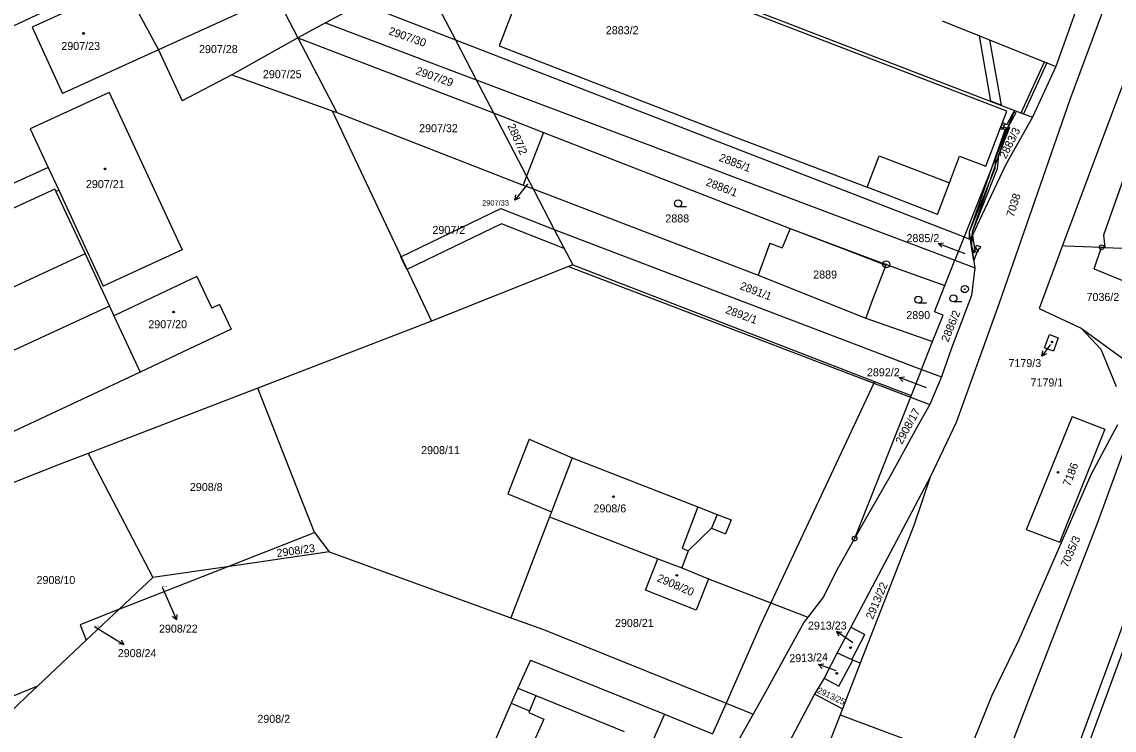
# Model space of a CAD drawing. Extents: x -593183 to -588034, y -1130415 to -1124994.
# Drawn here: x -591573.4 to -591341.4, y -1128134.3 to -1127983.9 of the extents above; entities that cross this region are included whole.
import ezdxf

# ---------------------------------------------------------------- set-up
doc = ezdxf.new("R2010")
doc.units = 0
for name, color, linetype in [('Vrstva 1', 7, 'Continuous'), ('Vrstva 16', 7, 'Continuous'), ('Vrstva 18', 7, 'Continuous'), ('Vrstva 19', 7, 'Continuous'), ('Vrstva 24', 7, 'Continuous'), ('Vrstva 25', 7, 'Continuous'), ('Vrstva 27', 7, 'Continuous'), ('Vrstva 4', 7, 'Continuous')]:
    doc.layers.add(name, color=color, linetype=linetype)

msp = doc.modelspace()

# ---------------------------------------------------------------- linework, layer by layer
at = {"layer": 'Vrstva 1'}
for p, q in [((-591318.29, -1127894.07), (-591353.86, -1127993.33)), ((-591317.66, -1127911.4), (-591350.8, -1128000.19)), ((-591527.67, -1127962.28), (-591514.76, -1127987.24)), ((-591467.59, -1127962.25), (-591362.61, -1128002.67)), ((-591462.75, -1127964.81), (-591472.01, -1127988.94)), ((-591327.4, -1127964.65), (-591344.16, -1128009.18)), ((-591553.24, -1127974.41), (-591673.98, -1128031.42)), ((-591551.76, -1127976.15), (-591571.16, -1127985)), ((-591551.76, -1127976.15), (-591544.34, -1127989.79)), ((-591289.77, -1127976.8), (-591349.4, -1128138.35)), ((-591520.52, -1127978.94), (-591544.34, -1127989.79)), ((-591501.18, -1127979.96), (-591508.9, -1127984.1)), ((-591501.18, -1127979.96), (-591481.32, -1127987.66)), ((-591485.52, -1127979.6), (-591481.32, -1127987.66)), ((-591571.16, -1127985), (-591564.7, -1127999.07)), ((-591508.9, -1127984.1), (-591514.76, -1127987.24)), ((-591508.9, -1127984.1), (-591476.88, -1127996.17)), ((-591377.94, -1127983.65), (-591353.86, -1127993.33)), ((-591514.76, -1127987.24), (-591528.79, -1127995.15)), ((-591514.76, -1127987.24), (-591473.22, -1128003.19)), ((-591514.76, -1127987.24), (-591506.5, -1128003.12)), ((-591481.32, -1127987.66), (-591476.88, -1127996.17)), ((-591481.32, -1127987.66), (-591373.3, -1128029.54)), ((-591544.34, -1127989.79), (-591564.7, -1127999.07)), ((-591544.34, -1127989.79), (-591539.32, -1128000.67)), ((-591353.86, -1127993.33), (-591358.81, -1128004.13)), ((-591528.79, -1127995.15), (-591539.32, -1128000.67)), ((-591528.79, -1127995.15), (-591507.49, -1128002.77)), ((-591476.88, -1127996.17), (-591473.22, -1128003.19)), ((-591476.88, -1127996.17), (-591375.26, -1128034.5)), ((-591554.81, -1127998.91), (-591571.56, -1128006.6)), ((-591554.81, -1127998.91), (-591539.33, -1128032.27)), ((-591350.8, -1128000.19), (-591365.86, -1128043.58)), ((-591333.81, -1128001.04), (-591343.68, -1128029.17)), ((-591507.49, -1128002.77), (-591506.5, -1128003.12)), ((-591507.49, -1128002.77), (-591486.4, -1128047.45)), ((-591506.5, -1128003.12), (-591466.91, -1128018.52)), ((-591473.22, -1128003.19), (-591462.58, -1128007.34)), ((-591473.22, -1128003.19), (-591466.19, -1128016.67)), ((-591362.61, -1128002.67), (-591373.3, -1128029.54)), ((-591368.7, -1128014.53), (-591364.24, -1128002.85)), ((-591362.61, -1128002.67), (-591358.81, -1128004.13)), ((-591358.81, -1128004.13), (-591364.45, -1128014.17)), ((-591571.56, -1128006.6), (-591567.77, -1128014.77)), ((-591462.58, -1128007.34), (-591466.19, -1128016.67)), ((-591462.58, -1128007.34), (-591410.23, -1128027.74)), ((-591344.16, -1128009.18), (-591352.42, -1128031.38)), ((-591376.42, -1128018.07), (-591374.27, -1128012.37)), ((-591374.27, -1128012.37), (-591368.7, -1128014.53)), ((-591567.77, -1128014.77), (-591577.51, -1128019.24)), ((-591567.77, -1128014.77), (-591565.52, -1128019.65)), ((-591364.45, -1128014.17), (-591369.53, -1128024.89)), ((-591466.19, -1128016.67), (-591466.91, -1128018.52)), ((-591466.19, -1128016.67), (-591464.81, -1128019.33)), ((-591566.36, -1128019.38), (-591623.78, -1128045.8)), ((-591566.36, -1128019.38), (-591566.11, -1128019.92)), ((-591565.52, -1128019.65), (-591566.11, -1128019.92)), ((-591566.11, -1128019.92), (-591559.94, -1128033.16)), ((-591565.52, -1128019.65), (-591556.09, -1128040.03)), ((-591466.91, -1128018.52), (-591464.81, -1128019.33)), ((-591464.81, -1128019.33), (-591417.01, -1128037.68)), ((-591464.81, -1128019.33), (-591460.31, -1128027.95)), ((-591378.98, -1128024.81), (-591393.89, -1128019)), ((-591378.98, -1128024.81), (-591376.42, -1128018.07)), ((-591369.53, -1128024.89), (-591371.94, -1128030.07)), ((-591460.31, -1128027.95), (-591456.4, -1128035.45)), ((-591460.31, -1128027.95), (-591382.32, -1128057.66)), ((-591410.23, -1128027.74), (-591411.94, -1128031.87)), ((-591410.23, -1128027.74), (-591389.83, -1128035.38)), ((-591343.68, -1128029.17), (-591343.41, -1128031.78)), ((-591414.55, -1128030.87), (-591417.01, -1128037.68)), ((-591414.55, -1128030.87), (-591411.94, -1128031.87)), ((-591373.3, -1128029.54), (-591375.26, -1128034.5)), ((-591373.3, -1128029.54), (-591371.94, -1128030.07)), ((-591371.94, -1128030.07), (-591371.04, -1128036.09)), ((-591352.42, -1128031.38), (-591357.39, -1128044.74)), ((-591352.42, -1128031.38), (-591351.76, -1128031.41)), ((-591351.76, -1128031.41), (-591344.12, -1128031.75)), ((-591345.72, -1128036.35), (-591344.12, -1128031.75)), ((-591344.12, -1128031.75), (-591343.41, -1128031.78)), ((-591559.94, -1128033.16), (-591599.4, -1128051.4)), ((-591559.94, -1128033.16), (-591554.77, -1128044.23)), ((-591539.33, -1128032.27), (-591556.09, -1128040.03)), ((-591343.41, -1128031.78), (-591326.94, -1128032.5)), ((-591457.32, -1128035.82), (-591486.4, -1128047.45)), ((-591456.4, -1128035.45), (-591457.32, -1128035.82)), ((-591457.32, -1128035.82), (-591392.49, -1128060.57)), ((-591389.95, -1128035.52), (-591393.01, -1128043.64)), ((-591389.83, -1128035.38), (-591389.95, -1128035.52)), ((-591389.83, -1128035.38), (-591377.41, -1128039.89)), ((-591377.41, -1128039.89), (-591375.26, -1128034.5)), ((-591375.26, -1128034.5), (-591371.04, -1128036.09)), ((-591371.04, -1128036.09), (-591371.74, -1128041.95)), ((-591345.72, -1128036.35), (-591329.58, -1128042.89)), ((-591536.19, -1128037.97), (-591553.8, -1128046.31)), ((-591536.19, -1128037.97), (-591533.03, -1128044.65)), ((-591417.01, -1128037.68), (-591394.2, -1128046.78)), ((-591371.74, -1128041.95), (-591375.97, -1128053.19)), ((-591554.77, -1128044.23), (-591594.16, -1128062.43)), ((-591554.77, -1128044.23), (-591553.8, -1128046.31)), ((-591531.36, -1128043.86), (-591533.03, -1128044.65)), ((-591531.36, -1128043.86), (-591528.89, -1128049.13)), ((-591393.01, -1128043.64), (-591394.2, -1128046.78)), ((-591365.86, -1128043.58), (-591374.99, -1128068.94)), ((-591357.39, -1128044.74), (-591348.46, -1128048.94)), ((-591553.8, -1128046.31), (-591548.21, -1128058.27)), ((-591486.4, -1128047.45), (-591523.28, -1128061.64)), ((-591394.2, -1128046.78), (-591379.99, -1128051.78)), ((-591528.89, -1128049.13), (-591548.21, -1128058.27)), ((-591356.22, -1128053.08), (-591355.17, -1128050.27)), ((-591355.17, -1128050.27), (-591353.3, -1128050.97)), ((-591348.46, -1128048.94), (-591344.28, -1128053.4)), ((-591348.46, -1128048.94), (-591337.8, -1128056.63)), ((-591382.32, -1128057.66), (-591379.99, -1128051.78)), ((-591353.3, -1128050.97), (-591354.34, -1128053.77)), ((-591375.97, -1128053.19), (-591378.13, -1128059.26)), ((-591354.34, -1128053.77), (-591356.22, -1128053.08)), ((-591344.28, -1128053.4), (-591341.04, -1128061.29)), ((-591548.21, -1128058.27), (-591602.93, -1128083.84)), ((-591382.32, -1128057.66), (-591384.52, -1128063.22)), ((-591382.32, -1128057.66), (-591378.13, -1128059.26)), ((-591378.13, -1128059.26), (-591380.46, -1128064.79)), ((-591523.28, -1128061.64), (-591559.28, -1128075.5)), ((-591511.23, -1128092.29), (-591523.28, -1128061.64)), ((-591392.49, -1128060.57), (-591384.66, -1128063.56)), ((-591384.66, -1128063.56), (-591396.57, -1128093.61)), ((-591384.52, -1128063.22), (-591384.66, -1128063.56)), ((-591384.66, -1128063.56), (-591380.59, -1128065.11)), ((-591335.23, -1128063.42), (-591345.05, -1128090.42)), ((-591380.59, -1128065.11), (-591383.26, -1128069.89)), ((-591380.46, -1128064.79), (-591380.59, -1128065.11)), ((-591350.39, -1128067.64), (-591359.66, -1128090.51)), ((-591350.39, -1128067.64), (-591343.45, -1128070.34)), ((-591383.26, -1128069.89), (-591389.02, -1128080.33)), ((-591374.99, -1128068.94), (-591380.52, -1128080.58)), ((-591343.45, -1128070.34), (-591352.47, -1128092.99)), ((-591340.75, -1128069.47), (-591346.41, -1128080.07)), ((-591465.63, -1128072.51), (-591470.14, -1128084.1)), ((-591465.63, -1128072.51), (-591456.51, -1128076.44)), ((-591559.28, -1128075.5), (-591565.82, -1128078)), ((-591559.28, -1128075.5), (-591545.54, -1128101.87)), ((-591565.82, -1128078), (-591649.36, -1128110.92)), ((-591456.51, -1128076.44), (-591429.84, -1128086.85)), ((-591389.02, -1128080.33), (-591393.05, -1128087.37)), ((-591346.41, -1128080.07), (-591361.7, -1128115.12)), ((-591380.52, -1128080.58), (-591397.34, -1128112.43)), ((-591380.52, -1128080.58), (-591383.99, -1128090.81)), ((-591470.14, -1128084.1), (-591460.88, -1128087.92)), ((-591327.13, -1128083.52), (-591347.63, -1128139.13)), ((-591429.84, -1128086.85), (-591425.75, -1128088.45)), ((-591393.05, -1128087.37), (-591396.57, -1128093.61)), ((-591461.3, -1128088.95), (-591469.51, -1128110.39)), ((-591460.88, -1128087.92), (-591461.3, -1128088.95)), ((-591461.3, -1128088.95), (-591438.31, -1128097.88)), ((-591425.75, -1128088.45), (-591422.77, -1128089.62)), ((-591422.77, -1128089.62), (-591423.93, -1128092.59)), ((-591426.91, -1128091.42), (-591431.86, -1128096.17)), ((-591426.91, -1128091.42), (-591423.93, -1128092.59)), ((-591383.99, -1128090.81), (-591395.38, -1128120.07)), ((-591359.66, -1128090.51), (-591360.14, -1128091.69)), ((-591360.14, -1128091.69), (-591353, -1128094.33)), ((-591345.05, -1128090.42), (-591359.82, -1128128.47)), ((-591529.74, -1128099.58), (-591511.23, -1128092.29)), ((-591511.23, -1128092.29), (-591508.14, -1128096.44)), ((-591396.57, -1128093.61), (-591400.63, -1128100.79)), ((-591352.47, -1128092.99), (-591353, -1128094.33)), ((-591509.53, -1128096.64), (-591529.74, -1128099.58)), ((-591508.14, -1128096.44), (-591509.53, -1128096.64)), ((-591508.14, -1128096.44), (-591469.51, -1128110.39)), ((-591431.86, -1128096.17), (-591433.26, -1128099.84)), ((-591438.31, -1128097.88), (-591433.26, -1128099.84)), ((-591552.71, -1128108.62), (-591529.74, -1128099.58)), ((-591529.74, -1128099.58), (-591545.54, -1128101.87)), ((-591433.26, -1128099.84), (-591427.6, -1128102.17)), ((-591400.63, -1128100.79), (-591403.14, -1128105.98)), ((-591545.54, -1128101.87), (-591552.71, -1128108.62)), ((-591427.6, -1128102.17), (-591414.32, -1128107.21)), ((-591414.32, -1128107.21), (-591406.45, -1128110.28)), ((-591403.14, -1128105.98), (-591406.45, -1128110.28)), ((-591552.71, -1128108.62), (-591560.99, -1128111.89)), ((-591552.71, -1128108.62), (-591559.68, -1128115.19)), ((-591469.51, -1128110.39), (-591462.57, -1128112.89)), ((-591406.45, -1128110.28), (-591407.23, -1128111.29)), ((-591560.99, -1128111.89), (-591559.68, -1128115.19)), ((-591462.57, -1128112.89), (-591423.83, -1128128.57)), ((-591407.23, -1128111.29), (-591415.39, -1128126.09)), ((-591397.34, -1128112.43), (-591400.22, -1128117.89)), ((-591397.34, -1128112.43), (-591394.4, -1128113.97)), ((-591559.68, -1128115.19), (-591570.02, -1128124.92)), ((-591397.17, -1128119.29), (-591394.4, -1128113.97)), ((-591361.7, -1128115.12), (-591367.39, -1128126.92)), ((-591465.35, -1128119.41), (-591468.07, -1128125.36)), ((-591465.35, -1128119.41), (-591436.9, -1128130.85)), ((-591400.22, -1128117.89), (-591403.02, -1128123.21)), ((-591400.22, -1128117.89), (-591397.17, -1128119.29)), ((-591399.87, -1128124.93), (-591396.9, -1128119.41)), ((-591396.9, -1128119.41), (-591397.17, -1128119.29)), ((-591395.38, -1128120.07), (-591396.9, -1128119.41)), ((-591395.38, -1128120.07), (-591399.14, -1128129.73)), ((-591403.02, -1128123.21), (-591405.04, -1128126.64)), ((-591403.02, -1128123.21), (-591399.87, -1128124.93)), ((-591570.02, -1128124.92), (-591630.51, -1128149.5)), ((-591570.02, -1128124.92), (-591572.28, -1128127.04)), ((-591468.07, -1128125.36), (-591469.47, -1128128.57)), ((-591415.39, -1128126.09), (-591418.1, -1128130.89)), ((-591405.04, -1128126.64), (-591412.55, -1128140.74)), ((-591405.04, -1128126.64), (-591404.88, -1128126.73)), ((-591404.88, -1128126.73), (-591399.14, -1128129.73)), ((-591572.28, -1128127.04), (-591581.11, -1128135.51)), ((-591469.47, -1128128.57), (-591478.53, -1128149.36)), ((-591423.83, -1128128.57), (-591418.1, -1128130.89)), ((-591359.82, -1128128.47), (-591382.83, -1128188.08)), ((-591367.39, -1128126.92), (-591373.09, -1128140.88)), ((-591436.9, -1128130.85), (-591426.69, -1128135.07)), ((-591418.37, -1128131.37), (-591421.57, -1128137.02)), ((-591418.1, -1128130.89), (-591418.37, -1128131.37)), ((-591399.65, -1128131.04), (-591411.36, -1128161.14)), ((-591399.14, -1128129.73), (-591399.65, -1128131.04)), ((-591399.65, -1128131.04), (-591373.09, -1128140.88))]:
    msp.add_line(p, q, dxfattribs=at)
for points in [[(-591364.24, -1128002.85), (-591411.69, -1127984.59), (-591462.75, -1127964.81)], [(-591472.01, -1127988.94), (-591420.94, -1128008.75), (-591393.89, -1128019)], [(-591379.99, -1128051.78), (-591377.77, -1128046.19), (-591379.62, -1128045.45), (-591377.41, -1128039.89)], [(-591427.6, -1128102.17), (-591430.22, -1128108.8), (-591440.91, -1128104.58), (-591438.31, -1128097.88)]]:
    msp.add_lwpolyline(points, dxfattribs=at)
at = {"layer": 'Vrstva 16'}
for p, q in [((-591466.02, -1128018.35), (-591466.82, -1128019.37)), ((-591373.09, -1128033.17), (-591376.02, -1128032.02)), ((-591381.29, -1128061.57), (-591384.29, -1128060.45)), ((-591543.53, -1128103.88), (-591541.72, -1128108.11)), ((-591557.96, -1128112.28), (-591554.24, -1128114.52)), ((-591396.9, -1128115.72), (-591397.9, -1128115.04)), ((-591400.48, -1128121.67), (-591401.39, -1128121.35))]:
    msp.add_line(p, q, dxfattribs=at)
at = {"layer": 'Vrstva 24'}
for centre, radius in [((-591344.12, -1128031.75), 0.5), ((-591344.12, -1128031.75), 0.0327), ((-591389.83, -1128035.38), 0.75), ((-591389.83, -1128035.38), 0.0903), ((-591373.15, -1128040.63), 0.75), ((-591373.15, -1128040.63), 0.0903), ((-591396.57, -1128093.61), 0.5), ((-591396.57, -1128093.61), 0.0327)]:
    msp.add_circle(centre, radius, dxfattribs=at)
at = {"layer": 'Vrstva 25'}
for p, q in [((-591466.82, -1128019.37), (-591468.66, -1128021.74)), ((-591432.27, -1128023.18), (-591434.02, -1128023.18)), ((-591376.02, -1128032.02), (-591378.81, -1128030.92)), ((-591381.28, -1128043.62), (-591383.03, -1128043.62)), ((-591373.81, -1128043.35), (-591375.56, -1128043.35)), ((-591355.02, -1128052.43), (-591356.77, -1128054.87)), ((-591384.29, -1128060.45), (-591387.1, -1128059.4)), ((-591541.72, -1128108.11), (-591540.54, -1128110.87)), ((-591554.24, -1128114.52), (-591551.67, -1128116.06)), ((-591397.9, -1128115.04), (-591400.38, -1128113.35)), ((-591401.39, -1128121.35), (-591404.22, -1128120.35))]:
    msp.add_line(p, q, dxfattribs=at)
for points in [[(-591467.65, -1128021.26), (-591468.66, -1128021.74), (-591468.44, -1128020.64)], [(-591378.06, -1128031.75), (-591378.81, -1128030.92), (-591377.7, -1128030.82)], [(-591355.78, -1128054.35), (-591356.77, -1128054.87), (-591356.59, -1128053.76)], [(-591386.34, -1128060.22), (-591387.1, -1128059.4), (-591385.99, -1128059.28)], [(-591540.47, -1128109.75), (-591540.54, -1128110.87), (-591541.39, -1128110.15)], [(-591552.27, -1128115.12), (-591551.67, -1128116.06), (-591552.78, -1128115.98)], [(-591399.83, -1128114.32), (-591400.38, -1128113.35), (-591399.27, -1128113.5)], [(-591403.44, -1128121.16), (-591404.22, -1128120.35), (-591403.11, -1128120.21)]]:
    msp.add_lwpolyline(points, dxfattribs=at)
for centre, radius in [((-591560.25, -1127986.34), 0.175), ((-591560.25, -1127986.34), 0.15), ((-591555.69, -1128015.09), 0.175), ((-591555.69, -1128015.09), 0.15), ((-591434.02, -1128022.43), 0.75), ((-591383.03, -1128042.87), 0.75), ((-591375.56, -1128042.6), 0.75), ((-591541.14, -1128045.49), 0.175), ((-591541.14, -1128045.49), 0.15), ((-591354.64, -1128051.84), 0.175), ((-591354.64, -1128051.84), 0.15), ((-591353.35, -1128079.52), 0.175), ((-591353.35, -1128079.52), 0.15), ((-591447.75, -1128084.71), 0.175), ((-591447.75, -1128084.71), 0.15), ((-591434.31, -1128101.41), 0.175), ((-591434.31, -1128101.41), 0.15), ((-591397.41, -1128116.76), 0.175), ((-591397.41, -1128116.76), 0.15), ((-591400.33, -1128122.2), 0.175), ((-591400.33, -1128122.2), 0.15)]:
    msp.add_circle(centre, radius, dxfattribs=at)
at = {"layer": 'Vrstva 27'}
for p, q in [((-591367.62, -1128000.74), (-591370.05, -1127986.82)), ((-591370.05, -1127986.82), (-591367.88, -1127987.69)), ((-591367.88, -1127987.69), (-591365.46, -1128001.57)), ((-591361.18, -1128003.22), (-591356.23, -1127992.38)), ((-591355.77, -1127992.56), (-591360.71, -1128003.4)), ((-591356.23, -1127992.38), (-591355.77, -1127992.56)), ((-591365.46, -1128001.57), (-591367.62, -1128000.74)), ((-591364.17, -1128005.59), (-591362.76, -1128002.99)), ((-591362.31, -1128003.2), (-591363.95, -1128006.14)), ((-591362.76, -1128002.99), (-591362.74, -1128003)), ((-591362.74, -1128003), (-591362.31, -1128003.2)), ((-591360.71, -1128003.4), (-591361.18, -1128003.22)), ((-591365.64, -1128006.53), (-591365.32, -1128005.69)), ((-591365.47, -1128006.25), (-591365.12, -1128005.28)), ((-591365.32, -1128005.69), (-591364.83, -1128005.91)), ((-591365.12, -1128005.28), (-591364.66, -1128005.44)), ((-591364.91, -1128006.17), (-591365, -1128006.42)), ((-591364.83, -1128005.91), (-591364.91, -1128006.17)), ((-591364.3, -1128006.52), (-591364.91, -1128006.17)), ((-591364.91, -1128006.17), (-591364.12, -1128006.47)), ((-591364.66, -1128005.44), (-591364.73, -1128005.67)), ((-591364.73, -1128005.67), (-591364.17, -1128005.59)), ((-591363.95, -1128006.14), (-591363.68, -1128006.3)), ((-591366.89, -1128013.43), (-591364.12, -1128006.47)), ((-591364.12, -1128006.47), (-591366.89, -1128013.43)), ((-591366.89, -1128013.43), (-591364.6, -1128006.79)), ((-591366.47, -1128012.21), (-591364.3, -1128006.52)), ((-591363.68, -1128006.3), (-591365.97, -1128012.29)), ((-591363.98, -1128006.53), (-591365.97, -1128012.29)), ((-591365.19, -1128006.73), (-591365.64, -1128006.53)), ((-591365, -1128006.42), (-591365.47, -1128006.25)), ((-591365.11, -1128006.55), (-591365.19, -1128006.73)), ((-591364.6, -1128006.79), (-591365.11, -1128006.55)), ((-591364.12, -1128006.47), (-591363.98, -1128006.53)), ((-591365.97, -1128012.29), (-591371.61, -1128028.5)), ((-591366.74, -1128014.95), (-591366.49, -1128012.43)), ((-591366.49, -1128012.43), (-591366.47, -1128012.21)), ((-591365.97, -1128012.29), (-591366.26, -1128015.09)), ((-591372.13, -1128028.44), (-591366.89, -1128013.43)), ((-591372.13, -1128028.44), (-591366.74, -1128014.95)), ((-591366.26, -1128015.09), (-591371.61, -1128028.5)), ((-591492.87, -1128033.75), (-591471.67, -1128023.48)), ((-591471.67, -1128023.48), (-591460.31, -1128027.95)), ((-591471.55, -1128026.76), (-591491.59, -1128036.46)), ((-591458.19, -1128032.01), (-591471.55, -1128026.76)), ((-591460.31, -1128027.95), (-591458.19, -1128032.01)), ((-591372.19, -1128029.97), (-591372.13, -1128028.44)), ((-591371.94, -1128030.07), (-591372.13, -1128028.44)), ((-591371.94, -1128030.07), (-591371.52, -1128029.17)), ((-591371.52, -1128029.17), (-591371.94, -1128030.07)), ((-591371.94, -1128030.07), (-591371.64, -1128029.43)), ((-591371.64, -1128029.43), (-591371.94, -1128030.07)), ((-591371.64, -1128029.43), (-591371.72, -1128031.56)), ((-591371.61, -1128028.5), (-591371.64, -1128029.43)), ((-591371.61, -1128028.5), (-591371.52, -1128029.17)), ((-591371.52, -1128029.17), (-591371.1, -1128032.1)), ((-591371.94, -1128030.07), (-591372.19, -1128029.97)), ((-591371.58, -1128032.47), (-591371.94, -1128030.07)), ((-591371.72, -1128031.56), (-591371.94, -1128030.07)), ((-591371.72, -1128031.56), (-591371.17, -1128032.92)), ((-591371.58, -1128032.47), (-591371.72, -1128031.56)), ((-591370.84, -1128031.77), (-591370.68, -1128031.31)), ((-591370.68, -1128031.31), (-591369.83, -1128031.6)), ((-591369.83, -1128031.6), (-591369.99, -1128032.06)), ((-591491.59, -1128036.46), (-591492.87, -1128033.75)), ((-591370.48, -1128032.85), (-591371.58, -1128032.47)), ((-591371.27, -1128034.55), (-591371.58, -1128032.47)), ((-591370.39, -1128032.22), (-591371.27, -1128034.55)), ((-591371.17, -1128032.92), (-591370.86, -1128032.05)), ((-591371.1, -1128032.1), (-591370.78, -1128032.21)), ((-591370.86, -1128032.05), (-591370.39, -1128032.22)), ((-591370.65, -1128031.86), (-591370.84, -1128031.77)), ((-591370.78, -1128032.21), (-591370.65, -1128031.86)), ((-591370.18, -1128032.03), (-591370.48, -1128032.85)), ((-591369.99, -1128032.06), (-591370.18, -1128032.03))]:
    msp.add_line(p, q, dxfattribs=at)
at = {"layer": 'Vrstva 4'}
for p, q in [((-591393.89, -1128019), (-591391.34, -1128012.33)), ((-591391.34, -1128012.33), (-591376.42, -1128018.07)), ((-591410.23, -1128027.74), (-591398.72, -1128032.15)), ((-591398.72, -1128032.15), (-591389.95, -1128035.52)), ((-591456.4, -1128035.45), (-591392.32, -1128060.21)), ((-591392.49, -1128060.57), (-591414.32, -1128107.21)), ((-591392.32, -1128060.21), (-591392.49, -1128060.57)), ((-591392.32, -1128060.21), (-591384.52, -1128063.22)), ((-591456.51, -1128076.44), (-591460.88, -1128087.92)), ((-591429.84, -1128086.85), (-591433.18, -1128095.66)), ((-591425.75, -1128088.45), (-591426.91, -1128091.42)), ((-591433.18, -1128095.66), (-591431.86, -1128096.17)), ((-591414.32, -1128107.21), (-591416.47, -1128111.8)), ((-591416.47, -1128111.8), (-591423.83, -1128128.57)), ((-591468.07, -1128125.36), (-591464.22, -1128126.93)), ((-591469.47, -1128128.57), (-591465.54, -1128130.17)), ((-591464.22, -1128126.93), (-591465.54, -1128130.17)), ((-591464.22, -1128126.93), (-591445.47, -1128134.57)), ((-591423.83, -1128128.57), (-591426.69, -1128135.07)), ((-591465.54, -1128130.17), (-591465.69, -1128130.54)), ((-591465.69, -1128130.54), (-591462.54, -1128131.96)), ((-591436.9, -1128130.85), (-591439.59, -1128136.97)), ((-591462.54, -1128131.96), (-591465.45, -1128138.44))]:
    msp.add_line(p, q, dxfattribs=at)

# ---------------------------------------------------------------- texts
at = {"layer": 'Vrstva 16'}
for s, height, p in [('2907/33', 1.14, (-591475.63, -1128022.88)), ('2885/2', 1.7, (-591385.53, -1128030.65)), ('7179/3', 1.7, (-591363.88, -1128057.18)), ('2892/2', 1.7, (-591393.93, -1128059.13)), ('7179/1', 1.7, (-591359.2, -1128061.29)), ('2908/22', 1.7, (-591544.24, -1128113.58)), ('2913/23', 1.7, (-591406.46, -1128112.92)), ('2908/24', 1.7, (-591552.99, -1128118.77))]:
    msp.add_text(s, height=height, dxfattribs=at).set_placement(p)
msp.add_text('2913/24', height=1.7, rotation=2.2453, dxfattribs=at).set_placement((-591410.38, -1128119.89))
at = {"layer": 'Vrstva 18'}
for s, height, rotation, p in [('2907/30', 1.7, 340.594, (-591495.63, -1127986.49)), ('2907/29', 1.7, 340.594, (-591489.88, -1127994.95)), ('2887/2', 1.7, 293.8388, (-591470.31, -1128005.94)), ('2883/3', 1.7, 63.435, (-591364.43, -1128013.07)), ('2885/1', 1.7, 339.3348, (-591425.48, -1128013.34)), ('2886/1', 1.7, 338.7099, (-591428.28, -1128018.54)), ('7038', 1.7, 72.4076, (-591362.78, -1128025.44)), ('2891/1', 1.7, 339.1435, (-591421.05, -1128040.59)), ('2892/1', 1.7, 339.7936, (-591424.1, -1128045.67)), ('2886/2', 1.7, 67.8214, (-591376.67, -1128052)), ('2908/17', 1.7, 61.1226, (-591386.52, -1128073.74)), ('7035/3', 1.7, 66.6445, (-591351.33, -1128099.87)), ('2908/23', 1.7, 7.8792, (-591519.15, -1128097.54)), ('2913/22', 1.7, 66.8792, (-591392.69, -1128110.88)), ('2913/25', 1.3, 334.8407, (-591404.6, -1128126.29))]:
    msp.add_text(s, height=height, rotation=rotation, dxfattribs=at).set_placement(p)
for s, height, p in [('2907/28', 1.7, (-591535.74, -1127990.51)), ('2907/25', 1.7, (-591522.18, -1127995.84)), ('2907/32', 1.7, (-591489.01, -1128007.31)), ('2907/33', 0.1, (-591466.02, -1128018.35)), ('2888', 1.7, (-591436.73, -1128026.47)), ('2907/2', 1.7, (-591486.18, -1128028.91)), ('2885/2', 0.1, (-591373.32, -1128033.17)), ('2889', 1.7, (-591405.34, -1128038.38)), ('7036/2', 1.7, (-591347.31, -1128043.14)), ('2890', 1.7, (-591385.57, -1128046.99)), ('2892/2', 0.1, (-591381.52, -1128061.57)), ('2908/11', 1.7, (-591488.58, -1128075.67)), ('2908/8', 1.7, (-591537.68, -1128083.5)), ('2908/10', 1.7, (-591570.23, -1128103.25)), ('2908/22', 0.2, (-591543.53, -1128103.88)), ('2908/21', 1.7, (-591447.42, -1128112.36)), ('2908/24', 0.2, (-591557.96, -1128112.28)), ('2908/2', 1.7, (-591523.35, -1128132.72))]:
    msp.add_text(s, height=height, dxfattribs=at).set_placement(p)
at = {"layer": 'Vrstva 19'}
for s, height, p in [('2883/2', 1.7, (-591449.37, -1127986.5)), ('2907/23', 1.7, (-591564.97, -1127989.85)), ('2907/21', 1.7, (-591559.75, -1128019.17)), ('2907/20', 1.7, (-591546.5, -1128048.93)), ('7179/3', 0.1, (-591354.99, -1128052.4)), ('2908/6', 1.7, (-591451.99, -1128088.04)), ('2913/23', 0.1, (-591397.15, -1128115.72)), ('2913/24', 0.1, (-591400.48, -1128121.67))]:
    msp.add_text(s, height=height, dxfattribs=at).set_placement(p)
for s, rotation, p in [('7186', 68.9625, (-591350.83, -1128082.62)), ('2908/20', 336.5771, (-591438.63, -1128102.59))]:
    msp.add_text(s, height=1.7, rotation=rotation, dxfattribs=at).set_placement(p)

doc.saveas('drawing.dxf')
